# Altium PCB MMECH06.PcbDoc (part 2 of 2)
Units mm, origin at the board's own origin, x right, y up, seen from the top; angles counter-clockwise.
Board outline 65 x 56.01 mm, 4 copper layers (Top Layer, Ground Plane, Mid Layer 1, Bottom Layer), stack 1.442 mm thick; 107 components, 79 nets, 362 pads, 608 vias.
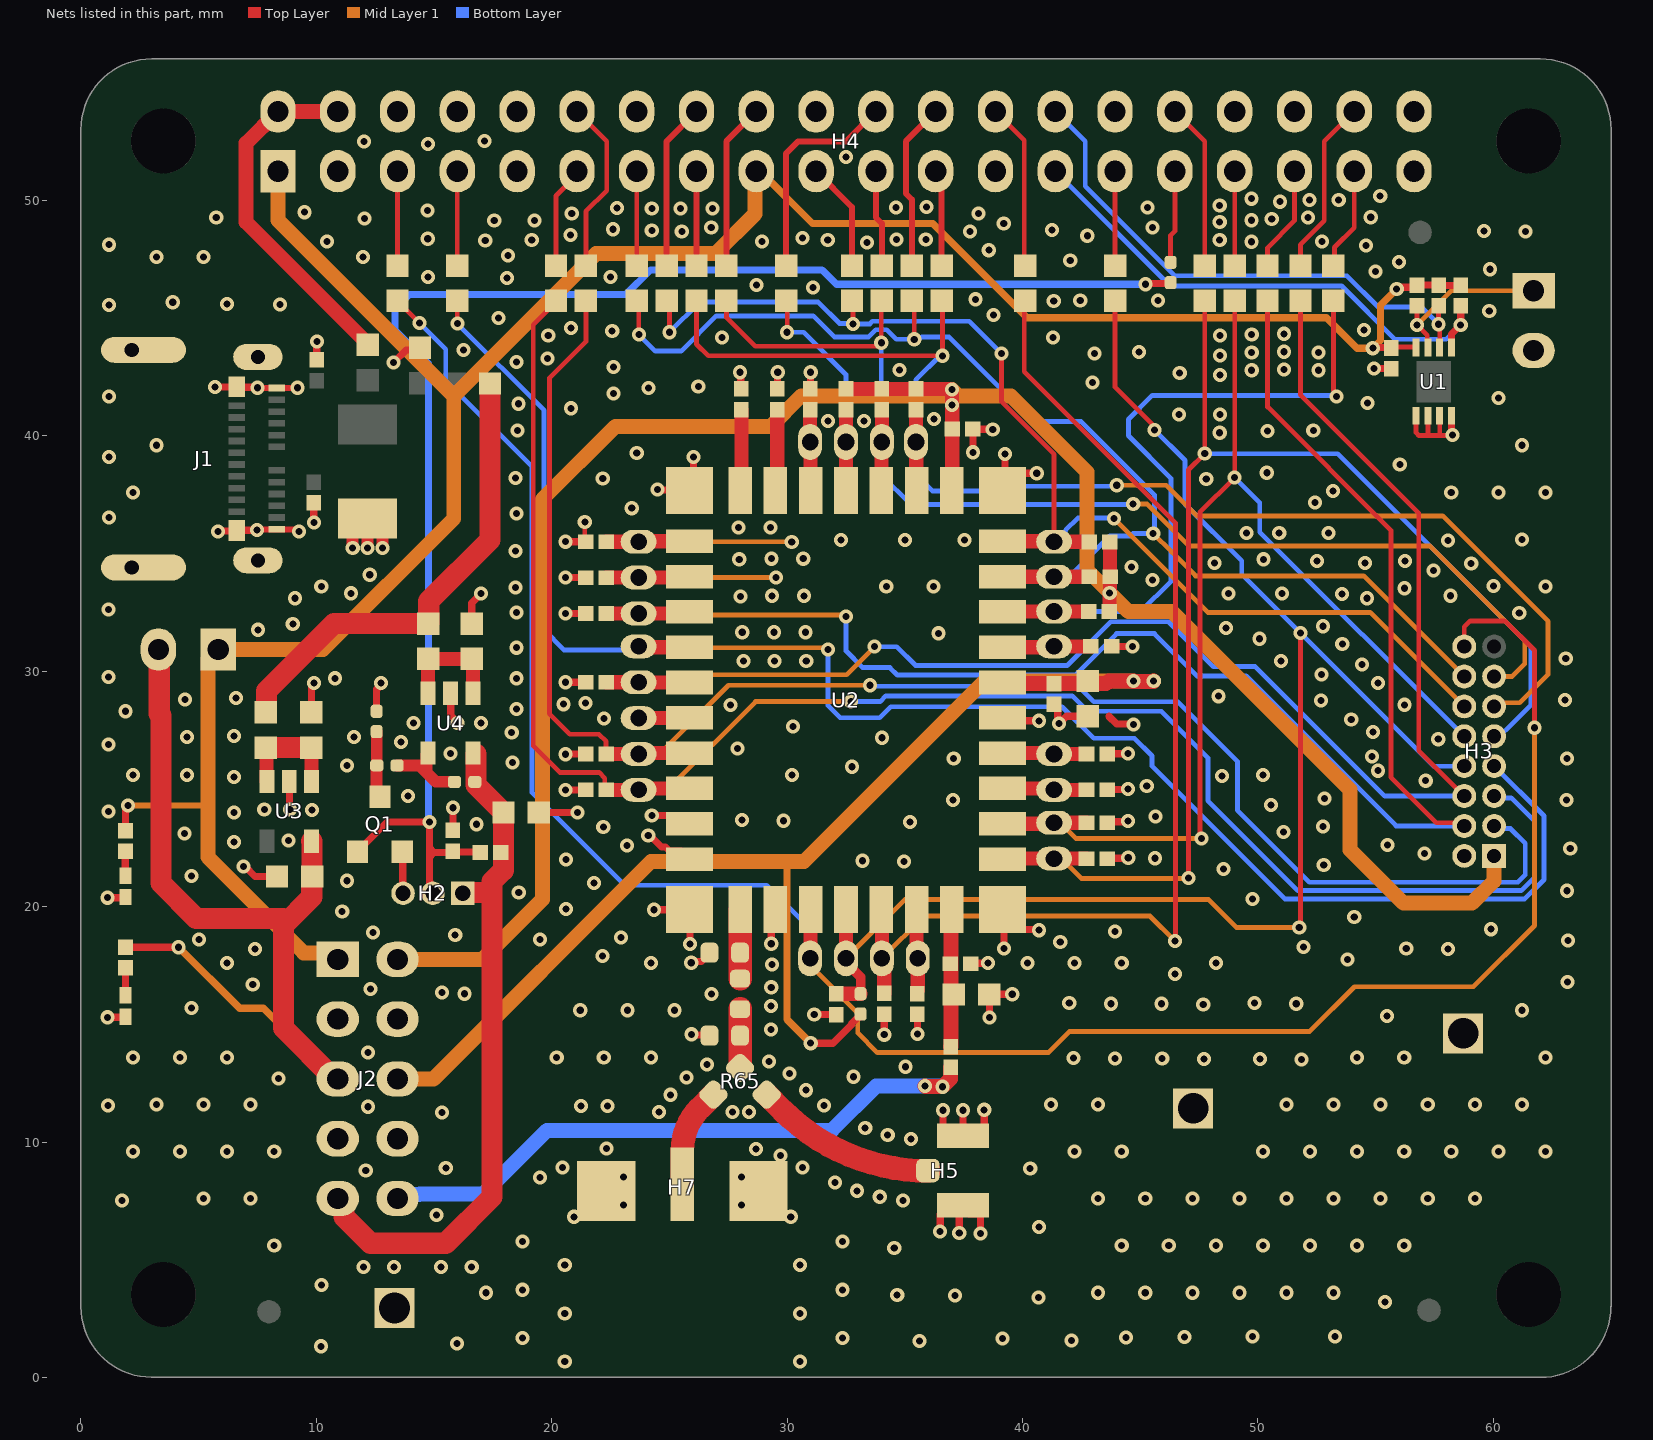
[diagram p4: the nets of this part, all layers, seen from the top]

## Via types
v1: diameter 0.6, hole 0.3, Top Layer to Bottom Layer, tented both sides, 608 vias

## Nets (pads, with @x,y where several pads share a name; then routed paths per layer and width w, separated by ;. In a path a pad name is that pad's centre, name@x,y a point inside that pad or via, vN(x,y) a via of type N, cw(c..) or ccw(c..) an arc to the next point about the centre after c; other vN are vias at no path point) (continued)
GND: C1.2 C2.2 C3.2 C4.1 C5.2 C6.2 C7.2 C8.1 C9.1 C10.1 C11.1 C16.2 D1.K D2.K H1.2 H2.3 H3.2 H4.6 H4.9 H4.14 H4.20 H4.25 H4.30 H4.34 H4.39 H5.2 H5.3 H7.2 J1.A1 J1.A12 J1.B1 J1.B12 J1.SH1 J1.SH2 J1.SH3 J1.SH4 J2.3 J2.4 J2.7 J2.8 Q1.2 R4.2 R5.2 R6.2 R7.2 R8.2 R9.2 R10.2 R11.2 R12.2 R13.2 R14.2 R15.2 R16.2 R18.2 R20.2 R24.2 R52.2 R58.1 R59.2 R60.2 R63.2 R64.2 TP1.1 TP6.1 TP7.1 U1.1 U1.2 U1.3 U1.4 U2.1 U2.2 U2.3 U2.12 U2.20 U2.26 U2.31 U2.37 U3.2 U4.2 VS1.A | length 87
  Top Layer w0.203: v1(21.405,36.344) 21.405,35.536 R13.2@21.439,35.502 ; U1.1@56.718,40.85 56.718,40.133 56.837,40.014 57.163,40.014 ; U1.2@57.218,40.85 57.218,40.069 57.163,40.014 ; U1.3@57.718,40.85 57.718,40.018 57.722,40.014 ; v1(58.256,40.04) 58.23,40.014 57.722,40.014 ; 57.163,40.014 57.722,40.014
  Top Layer w0.254: v1(7.506,42.041) 7.512,42.036 8.323,42.036 J1.A1@8.329,42.03 8.335,42.036 9.189,42.036 v1(9.195,42.041) ; v1@7.508,36.028 J1.A12@8.327,36.028 ; J1.A12@8.329,36.03 9.103,36.03 9.192,35.941 v1(9.259,35.941)
  Top Layer w0.305: v1(1.131,15.3) 1.863,15.3 D2.K@1.893,15.33 ; v1(1.131,20.38) D1.K@1.975,20.38 ; v1(5.69,42.073) 5.693,42.077 6.626,42.077 J1.B12@6.629,42.08 6.648,42.061 7.487,42.061 v1(7.506,42.041) ; v1(5.83,35.941) 5.85,35.961 6.609,35.961 J1.B1@6.629,35.98 6.639,35.991 7.471,35.991 v1(7.481,36.001) v1@7.508,36.028 ; v1(6.9,21.7) 6.978,21.7 7.396,21.281 C9.1@8.329,21.281 ; U3.2@8.85,25.32 8.863,25.307 8.863,24.139 v1(8.875,24.126) ; C8.1@9.79,28.254 9.79,29.31 9.9,29.42 v1(9.9,29.5) ; v1(9.894,36.322) R60.2@9.894,37.16 ; R59.2@10.021,43.215 v1(10.021,44.002) ; VS1.A@11.254,36.363 11.381,36.49 11.39,36.481 VS1.A@12.18,36.481 ; VS1.A@12.143,36.444 VS1.A@12.18,36.481 ; R52.2@12.562,28.299 12.562,29.233 12.75,29.42 v1(12.75,29.5) ; VS1.A@12.798,35.863 VS1.A@12.18,36.481 ; v1(13.284,43.115) 13.818,43.648 14.491,43.648 C16.2@14.402,43.738 ; Q1.2@13.65,22.325 13.675,22.3 13.675,20.525 H2.3@13.7,20.5 ; U4.2@15.7,29.07 15.713,29.057 15.713,28.117 16,27.83 v1(16,27.8) ; R64.2@15.8,23.24 v1(15.8,24.2) ; C11.1@16.6,32.025 16.6,32.9 v1(17,33.3) ; C10.1@19.45,24 v1(21.1,24) ; v1(20.587,24.949) 20.594,24.955 21.46,24.955 R15.2@21.466,24.961 ; v1@20.613,26.473 20.619,26.479 21.434,26.479 R16.2@21.443,26.489 ; v1@20.861,29.533 R18.2@21.466,29.533 ; v1@20.861,32.454 R20.2@21.466,32.454 ; v1@20.861,33.978 R14.2@21.466,33.978 ; v1@20.861,35.502 R13.2@21.439,35.502 ; v1(24.1,23.025) 24.18,23.025 24.667,22.537 24.834,22.537 25.002,22.369 25.51,22.369 U2.2@25.858,22.021 ; v1(24.25,23.875) 24.256,23.869 25.502,23.869 U2.3@25.85,23.521 ; v1(24.347,19.869) 25.705,19.869 25.871,19.703 v1(25.871,18.421) ; v1(24.489,37.721) 24.509,37.702 U2.12@25.895,37.702 ; v1(25.927,17.618) 25.983,17.674 26.359,17.674 26.551,17.866 R58.1@26.551,18.037 ; v1(25.933,14.578) 25.961,14.549 26.678,14.549 R63.2@26.7,14.571 ; U2.12@26.023,37.844 v1(26.023,39.104) ; v1(28,42.7) 28.028,42.672 28.028,42.11 R12.2@28.055,42.082 ; v1(29.325,18.425) 29.325,19.854 U2.37@29.5,20.029 ; R11.2@29.579,41.982 29.59,41.993 29.59,42.69 v1(29.6,42.7) ; R10.2@30.976,42.082 30.988,42.094 30.988,42.688 v1(31,42.7) ; v1(31.15,15.425) 31.155,15.42 C7.2@32.089,15.42 ; R4.2@33.964,15.373 34.126,15.211 v1(34.126,14.56) ; v1(35.533,14.598) R24.2@35.533,15.436 ; v1(36.496,6.208) 36.503,6.215 36.503,6.942 36.638,7.076 37.698,7.076 H5.3@37.698,7.237 ; v1(36.62,11.352) 36.62,10.637 36.706,10.551 H5.2@36.73,10.551 ; v1(37.31,6.137) H5.3@37.31,6.942 ; H5.2@37.451,10.264 37.61,10.637 37.469,10.637 v1(37.469,11.352) ; H5.3@37.698,6.942 38.176,6.942 H5.3@38.4,7.166 ; C2.2@37.796,17.584 37.807,17.595 38.517,17.595 v1(38.532,17.61) ; C6.2@37.893,40.29 37.905,40.278 38.723,40.278 v1(38.735,40.267) ; v1(37.9,39.3) 37.897,39.303 37.897,40.294 C6.2@37.9,40.297 ; v1(38.211,6.12) 38.211,6.942 H5.3@38.229,6.942 ; H5.2@38.37,10.097 v1(38.37,11.37) ; v1(38.596,15.287) C3.2@38.596,16.233 ; C3.2@38.596,16.458 C3.2@38.641,16.503 ; C3.2@38.641,16.278 v1(39.561,16.278) ; U2.31@39.15,19.871 39.998,19.023 40.677,19.023 v1(40.7,19) ; U2.26@39.15,28.021 39.276,27.895 v1(40.704,27.895) ; U2.20@39.15,37.671 39.256,37.777 v1(39.256,39.223) ; v1(39.218,18.219) U2.31@39.218,19.796 ; U2.20@39.231,37.76 39.882,38.411 v1(40.603,38.411) ; C4.1@41.334,28.598 41.491,28.44 41.491,27.917 41.555,27.853 v1(41.555,27.773) 41.87,28.088 C5.2@42.766,28.088 ; R5.2@43.589,22.04 43.608,22.059 44.47,22.059 v1(44.489,22.078) ; R6.2@43.589,23.564 43.628,23.604 44.443,23.604 v1(44.482,23.644) ; R7.2@43.589,24.961 43.605,24.978 44.466,24.978 v1(44.482,24.995) ; R8.2@43.589,26.485 43.599,26.495 44.472,26.495 v1(44.482,26.506) ; 43.666,28.088 43.988,27.766 44.694,27.766 v1(44.717,27.743) ; R9.2@43.773,31.057 43.779,31.051 44.66,31.051 v1(44.667,31.045) ; v1(54.928,42.859) 54.932,42.855 55.661,42.855 C1.2@55.665,42.859 ; U1.4@58.218,40.85 58.218,40.077 v1(58.256,40.04)
  Top Layer w0.508: v1(11.545,35.243) VS1.A@11.545,36.481 ; v1(12.18,35.243) VS1.A@12.18,36.481 ; v1(12.815,35.243) VS1.A@12.815,36.481
  other v1: 20.552,0.675 30.552,0.675 10.2,1.325 15.975,1.45 35.625,1.55 42.075,1.575 39.15,1.65 18.752,1.675 32.352,1.675 44.4,1.7 46.875,1.725 49.772,1.743 53.267,1.743 20.552,2.725 30.552,2.725 55.4,3.2 40.675,3.4 37.125,3.475 34.675,3.5 17.211,3.599 43.211,3.599 45.211,3.599 47.211,3.599 49.211,3.599 51.211,3.599 53.211,3.599 18.752,3.725 32.352,3.725 10.225,3.925 12,4.7 13.3,4.7 15.3,4.7 16.6,4.7 20.552,4.775 30.552,4.775 34.55,5.5 8.211,5.599 44.211,5.599 46.211,5.599 48.211,5.599 50.211,5.599 52.211,5.599 54.211,5.599 56.211,5.599 18.752,5.775 32.352,5.775 40.7,6.4 20.952,6.825 30.152,6.825 15.1,6.9 23.052,7.325 28.052,7.325 1.75,7.525 34.923,7.518 5.211,7.599 7.211,7.599 43.211,7.599 45.211,7.599 47.211,7.599 49.211,7.599 51.211,7.599 53.211,7.599 55.211,7.599 57.211,7.599 59.211,7.599 33.935,7.675 32.968,7.93 32.031,8.279 19.5,8.5 23.052,8.525 28.052,8.525 12.1,8.8 40.325,8.875 15.5,8.9 20.452,8.925 30.652,8.925 29.725,9.425 2.211,9.599 4.211,9.599 6.211,9.599 8.211,9.599 42.211,9.599 44.211,9.599 50.211,9.599 52.211,9.599 54.211,9.599 56.211,9.599 58.211,9.599 60.211,9.599 62.211,9.599 28.675,9.7 22.325,9.725 35.256,10.123 34.271,10.299 33.316,10.595 15.338,11.25 24.553,11.27 27.675,11.275 28.386,11.27 12.2,11.5 21.25,11.525 22.368,11.525 1.15,11.55 31.57,11.559 3.211,11.599 5.211,11.599 7.211,11.599 41.211,11.599 43.211,11.599 51.211,11.599 53.211,11.599 55.211,11.599 57.211,11.599 59.211,11.599 61.211,11.599 25.051,12.007 30.804,12.203 8.4,12.7 25.732,12.74 32.825,12.775 30.098,12.91 35.025,13.2 26.6,13.299 29.236,13.418 51.85,13.5 47.7,13.525 50.082,13.525 43.925,13.55 45.932,13.55 42.157,13.575 2.211,13.599 4.211,13.599 6.211,13.599 20.211,13.599 22.211,13.599 24.211,13.599 54.211,13.599 56.211,13.599 62.211,13.599 12.2,13.8 29.317,14.781 55.475,15.35 21.211,15.599 23.211,15.599 25.211,15.599 61.211,15.599 4.7,15.7 29.315,15.781 47.675,15.85 43.75,15.875 45.907,15.875 51.625,15.875 41.982,15.9 49.857,15.9 16.3,16.3 26.794,16.289 15.338,16.35 12.3,16.5 29.325,16.575 7.3,16.7 63.15,16.8 46.47,17.145 29.35,17.55 6.211,17.599 24.211,17.599 40.211,17.599 42.211,17.599 44.211,17.599 48.211,17.599 53.8,17.75 22.15,17.9 7.4,18.2 58.068,18.2 56.3,18.225 51.931,18.288 41.6,18.5 63.175,18.568 5.018,18.598 19.5,18.6 22.94,18.69 15.9,18.8 12.4,18.9 43.93,18.945 59.897,19.042 54.09,19.558 11.1,19.8 20.6,19.9 49.775,20.325 18.6,20.6 63.125,20.675 21.8,21 11.3,21.1 4.7,21.3 48.543,21.593 52.795,21.777 34.968,21.925 33.2,21.95 20.6,22 45.625,22.057 57.075,22.25 63.265,22.477 23.2,22.6 55.5,22.625 6.5,22.75 8.814,22.804 4.4,23.1 51.084,23.176 22.19,23.39 52.769,23.403 16.8,23.5 35.211,23.599 29.843,23.65 28.075,23.675 45.65,23.825 6.5,24 1.168,24.039 9.815,24.101 7.789,24.129 50.55,24.325 37.05,24.525 63.1,24.525 52.825,24.6 13.9,24.7 45.275,25.125 57.125,25.35 6.5,25.5 48.475,25.55 2.211,25.599 4.5,25.6 30.211,25.599 50.211,25.599 55.096,25.775 32.757,25.943 11.3,26 18.329,26.129 37.075,26.293 63.125,26.293 54.839,26.376 20.587,26.473 15.7,26.5 27.898,26.716 1.168,26.884 13.6,27 57.658,27.113 34.025,27.175 4.5,27.2 11.6,27.2 6.5,27.25 18.3,27.4 54.889,27.418 30.25,27.65 14.126,27.8 17,27.8 53.963,27.954 22.225,27.998 1.9,28.3 18.5,28.4 27.589,28.569 56.225,28.575 20.5,28.6 21.438,28.659 52.68,28.764 63.05,28.775 4.421,28.805 6.587,28.865 48.324,28.94 55.096,29.499 20.587,29.533 10.8,29.7 18.5,29.7 1.168,29.754 52.705,29.856 54.42,30.286 28.143,30.437 29.464,30.437 30.81,30.437 50.978,30.44 63.075,30.543 18.5,31 53.582,31.15 50.063,31.38 36.437,31.612 28.092,31.656 29.439,31.656 30.785,31.656 7.518,31.761 48.641,31.837 52.769,31.912 9,32 20.587,32.454 61.1,32.475 18.5,32.5 1.168,32.625 9.1,33.1 54.625,33.1 28.016,33.18 29.362,33.205 30.709,33.205 58.179,33.207 53.575,33.275 11.481,33.31 48.75,33.3 51.025,33.3 56.225,33.525 18.454,33.563 10.211,33.599 34.211,33.599 36.211,33.599 62.211,33.599 60,33.625 45.525,33.875 20.587,33.978 12.268,34.098 57.455,34.276 44.633,34.426 59.058,34.58 48.158,34.604 54.547,34.601 52.502,34.682 56.25,34.675 27.965,34.755 50.228,34.755 29.337,34.78 30.683,34.78 18.454,35.112 20.587,35.502 58.075,35.55 32.283,35.568 35.001,35.568 37.541,35.568 61.211,35.599 49.518,35.871 50.902,35.871 53,35.875 27.94,36.101 29.286,36.101 1.194,36.536 18.5,36.7 23.4,36.925 52.425,37.175 2.211,37.599 58.211,37.599 60.211,37.599 62.211,37.599 53.192,37.659 47.803,38.162 22.168,38.193 18.454,38.211 50.375,38.432 56.025,38.775 1.194,39.102 23.61,39.265 3.211,39.599 61.211,39.599 48.375,40.132 50.4,40.2 18.542,40.219 52.35,40.225 31.738,40.637 33.262,40.637 36.234,40.713 46.65,40.907 48.387,40.905 20.816,41.17 18.593,41.362 54.65,41.4 60.211,41.599 1.194,41.667 22.625,41.8 24.118,42.029 26.226,42.089 42.977,42.269 48.387,42.581 46.675,42.675 49.733,42.785 52.578,42.785 34.775,42.8 51.105,42.81 22.625,42.918 18.505,43.138 19.825,43.291 48.387,43.42 43.053,43.496 49.733,43.547 52.578,43.547 44.946,43.561 51.105,43.572 16.256,43.648 27.225,44.175 41.3,44.182 19.851,44.256 48.387,44.258 49.733,44.309 51.105,44.334 22.569,44.459 54.5,44.5 20.816,44.577 17.742,45 38.765,45.135 59.825,45.307 1.194,45.553 8.45,45.575 6.211,45.599 3.9,45.675 41.325,45.725 42.45,45.75 45.75,45.75 38,45.8 31.1,46.3 28.7,46.4 18.1,46.7 14.75,46.75 22.5,46.75 54.992,46.985 59.85,47.075 55.992,47.385 42.025,47.447 3.211,47.599 5.211,47.599 11.975,47.6 18.15,47.668 38.565,47.885 54.592,48.085 1.194,48.119 33.389,48.218 10.45,48.25 28.925,48.25 49.721,48.244 52.725,48.25 17.175,48.3 19.15,48.325 31.725,48.325 48.375,48.32 34.646,48.347 35.89,48.347 14.732,48.373 30.65,48.4 42.75,48.5 20.8,48.525 25.525,48.675 37.775,48.675 61.368,48.675 59.6,48.7 24.25,48.725 41.25,48.75 22.6,48.775 26.775,48.85 45.525,48.85 39.2,49.025 48.375,49.082 17.557,49.15 19.275,49.15 49.721,49.158 50.585,49.209 12.05,49.225 5.75,49.275 52.125,49.275 54.792,49.285 20.85,49.45 38.125,49.45 9.5,49.5 14.725,49.575 24.25,49.65 25.475,49.65 26.825,49.65 22.775,49.675 34.62,49.693 45.3,49.7 35.916,49.719 48.375,49.784 50.94,49.946 52.185,50.022 53.43,50.022 49.721,50.073 55.192,50.185 32.5,51.851 14.75,52.4 12.025,52.5 17.15,52.525
MM_GPIO0: pad.16 R4.1 R30.1 U2.34 | length 46.5
  Top Layer w0.203: U2.34@34,20.016 cw(c34,19.992) U2.34@34.024,19.992 ; R30.1@40.076,45.682 40.076,42.724 46.495,36.305 46.495,18.568 v1(46.47,18.543)
  Top Layer w0.6: pad.16@34.024,17.803 34.024,17.436 34.124,17.337 R4.1@34.124,16.316 ; pad.16@34.024,18.535 U2.34@34.024,19.992
  Mid Layer 1 w0.203: pad.16@34.024,17.803 35.821,19.6 45.413,19.6 v1(46.47,18.543)
MM_GPIO1: pad.17 R24.1 U2.33 | length 3.3
  Top Layer w0.203: pad.17@35.5,17.851 pad.17@35.548,17.803
  Top Layer w0.6: pad.17@35.5,18.001 U2.33@35.5,19.871 ; R24.1@35.548,16.457 pad.17@35.548,17.803
MM_GPIO2: H3.9 pad.19 R5.1 R28.1 U2.30 | length 55.8
  Top Layer w0.203: U2.30@39,22.016 cw(c39.024,22.016) U2.30@39.024,22.04 ; v1(47.049,21.218) 47.049,38.552 v1(47.74,39.243) R28.1@47.74,45.682
  Top Layer w0.6: U2.30@39.324,22.04 pad.19@40.877,22.04 ; pad.19@41.341,22.04 R5.1@42.717,22.04
  Mid Layer 1 w0.203: pad.19@41.191,22.04 pad.19@41.266,22.115 ; pad.19@41.341,22.04 41.66,22.04 42.5,21.2 47.031,21.2 v1(47.049,21.218) v1@46.999,21.269
  Bottom Layer w0.203: v1(47.74,39.243) 53.388,39.243 61.583,31.048 61.583,28.559 60.519,27.495 60.511,27.495 60.254,27.238 H3.9@60.034,27.238
MM_GPIO3: H3.10 pad.20 R6.1 R29.1 U2.29 | length 48.3
  Top Layer w0.203: v1(47.603,22.9) 47.537,22.967 47.537,36.754 v1(49.01,38.227) R29.1@49.01,45.682
  Top Layer w0.6: U2.29@39.3,23.521 pad.20@41.139,23.521 ; pad.20@41.341,23.564 R6.1@42.717,23.564
  Mid Layer 1 w0.203: pad.20@41.191,23.564 pad.20@41.266,23.639 ; pad.20@41.341,23.564 41.595,23.564 42.259,22.9 v1(47.603,22.9)
  Bottom Layer w0.203: v1(49.01,38.227) 50.072,37.165 50.072,35.904 54.404,31.573 54.429,31.573 H3.10@58.764,27.238
MM_GPIO4: pad.21 R7.1 U2.28 | length 3.2
  Top Layer w0.6: U2.28@39.3,25.021 pad.21@41.122,25.021 ; pad.21@41.341,24.961 R7.1@42.717,24.961
MM_GPIO5: pad.22 R8.1 U2.27 | length 3.2
  Top Layer w0.6: U2.27@39.3,26.521 pad.22@41.146,26.521 ; pad.22@41.341,26.485 R8.1@42.717,26.485
MM_GPIO6: pad.24 R9.1 U2.24 | length 3.4
  Top Layer w0.6: U2.24@39.3,31.021 pad.24@41.146,31.021 ; pad.24@41.309,31.057 R9.1@42.909,31.057
MM_GPIO7: pad.34 R10.1 U2.15 | length 3.3
  Top Layer w0.6: pad.34@30.976,39.739 R10.1@30.976,40.958 ; U2.15@31,37.671 30.988,37.683 30.988,39.703 pad.34@31,39.715
MM_GPIO8: R11.1 U2.14 | length 3.5
  Top Layer w0.6: U2.14@29.5,37.671 29.579,37.75 R11.1@29.579,41.11
MM_GPIO9: R12.1 U2.13 | length 3.5
  Top Layer w0.6: U2.13@28,37.671 28.055,37.726 R12.1@28.055,41.11
MM_GPIO10: pad.2 R13.1 U2.11 | length 9.7
  Top Layer w0.6: R13.1@22.319,35.502 pad.2@23.691,35.502 ; pad.2@23.837,35.521 U2.11@25.7,35.521
  Mid Layer 1 w0.203: pad.2@23.682,35.5 30.193,35.5 v1(30.195,35.497)
MM_GPIO11: pad.3 R14.1 U2.10 | length 9.4
  Top Layer w0.6: R14.1@22.326,33.978 pad.3@23.672,33.978 ; pad.3@23.691,33.978 25.807,33.978 U2.10@25.85,34.021
  Mid Layer 1 w0.203: pad.3@23.691,33.983 29.515,33.983 v1(29.521,33.989)
MM_JTAG_TCK: H3.5 pad.12 R15.1 R42.1 U2.4 | length 75.6
  Top Layer w0.203: R42.1@20.181,45.682 20.131,45.682 19.808,45.359 19.808,45.309 19.216,44.717 19.216,26.826 20.342,25.7 22.01,25.7 22.253,25.457 22.253,25.019 R15.1@22.311,24.961
  Top Layer w0.6: R15.1@22.326,24.961 pad.12@23.672,24.961 ; pad.12@23.878,25.021 U2.4@25.7,25.021
  Mid Layer 1 w0.203: pad.12@23.691,24.961 24.911,24.961 28.66,28.71 v1(32.703,28.71)
  Bottom Layer w0.203: v1(32.703,28.71) 33.95,28.71 34.193,28.953 42.115,28.953 42.768,28.3 45.9,28.3 47.875,26.325 47.875,24.508 51.698,20.685 61.188,20.685 61.75,21.247 61.75,23.629 60.758,24.62 60.111,24.62 H3.5@60.034,24.698
MM_JTAG_TDI: H3.3 pad.11 R16.1 R44.1 U2.5 | length 71.4
  Top Layer w0.203: R44.1@21.451,45.682 21.451,44.002 19.9,42.451 19.9,28.2 20.775,27.325 22.002,27.325 22.311,27.016 R16.1@22.311,26.485
  Top Layer w0.6: R16.1@22.326,26.485 pad.11@23.672,26.485 ; pad.11@23.854,26.521 U2.5@25.7,26.521
  Mid Layer 1 w0.203: pad.11@23.691,26.485 23.741,26.535 24.638,26.535 27.509,29.406 v1(33.516,29.406)
  Bottom Layer w0.203: v1(33.516,29.406) 33.562,29.36 42.372,29.36 43.032,28.7 46.6,28.7 49.125,26.175 49.125,24.1 52.185,21.04 61.04,21.04 61.35,21.35 61.35,22.696 60.727,23.319 60.143,23.319 H3.3@60.034,23.428
MM_JTAG_TDO: H3.4 pad.7 R20.1 R45.1 U2.9 | length 71
  Top Layer w0.203: R45.1@50.407,45.682 50.407,41.227 55.65,35.984 55.65,25.5 57.583,23.567 58.625,23.567 H3.4@58.764,23.428
  Top Layer w0.6: R20.1@22.326,32.454 pad.7@23.672,32.454 ; pad.7@23.691,32.454 25.783,32.454 U2.9@25.85,32.521
  Mid Layer 1 w0.203: pad.7@23.691,32.39 32.437,32.39 v1(32.5,32.327)
  Bottom Layer w0.203: v1(32.5,32.327) 32.5,30.862 33.204,30.158 34.367,30.158 34.687,29.838 42.232,29.838 43.993,31.599 45.601,31.599 47.401,29.799 49.497,29.799 55.868,23.428 H3.4@58.764,23.428
MM_JTAG_TMS: H3.6 pad.4 R18.1 R43.1 U2.7 | length 67
  Top Layer w0.203: pad.4@23.672,29.533 pad.4@23.684,29.521 ; R43.1@51.804,45.682 51.804,41.746 56.833,36.717 56.833,26.628 H3.6@58.764,24.698
  Top Layer w0.6: R18.1@22.326,29.533 pad.4@23.672,29.533 ; pad.4@23.83,29.521 U2.7@25.7,29.521
  Mid Layer 1 w0.203: pad.4@23.697,29.533 25.895,29.533 26.213,29.851 32.522,29.851 v1(33.715,31.043)
  Bottom Layer w0.203: v1(33.715,31.043) 34.657,31.043 35.456,30.244 41.899,30.244 43.755,32.1 46.2,32.1 48.1,30.2 49.888,30.2 55.39,24.698 H3.6@58.764,24.698
MM_JTAG_TRST: H3.7 pad.9 R46.1 U2.8 | length 72.8
  Top Layer w0.203: v1(15.99,44.764) R46.1@15.99,45.682 ; pad.9@23.672,31.057 pad.9@23.708,31.021
  Top Layer w0.6: pad.9@23.854,31.021 U2.8@25.7,31.021
  Mid Layer 1 w0.203: pad.9@23.709,30.993 31.675,30.993 v1(31.738,30.93)
  Bottom Layer w0.203: v1(15.99,44.764) 19.673,41.081 19.673,31.753 20.519,30.907 pad.9@23.841,30.907 ; v1(31.738,30.93) 31.738,28.537 32.25,28.025 33.925,28.025 34.396,28.496 41.676,28.496 43.022,27.15 44.75,27.15 45.5,26.4 45.5,25.963 51.134,20.329 61.335,20.329 62.15,21.144 62.15,23.852 H3.7@60.034,25.968
MM_RESET_N: C7.1 H3.8 pad.15 R47.2 R49.1 U2.35 | length 64.9
  Top Layer w0.203: R49.1@44.2,45.462 R49.1@43.93,45.732 43.93,42.07 45.6,40.4 v1(45.6,40.256) ; v1(51.753,19.11) 51.804,19.161 v1(51.804,31.623)
  Top Layer w0.4: pad.15@32.5,17.803 32.5,17.633 33.12,17.013 R47.2@33.12,16.308
  Top Layer w0.6: C7.1@32.308,16.302 R47.2@33.115,16.302 ; pad.15@32.5,17.953 U2.35@32.5,19.871
  Mid Layer 1 w0.203: pad.15@32.5,17.803 34.997,20.3 47.9,20.3 49.09,19.11 v1(51.753,19.11) v1@51.74,19.097
  Bottom Layer w0.203: v1(45.6,40.256) 46.9,38.956 46.9,37.1 49.314,34.686 49.314,34.113 57.459,25.968 H3.8@58.764,25.968
MM_SD_CLK: H3.11 pad.35 R17.2 R32.2 R33.1 U2.18 | length 58.3
  Top Layer w0.203: R33.1@26.15,45.682 26.15,43.9 26.65,43.4 v1(36.6,43.4) 36.6,45.646 R32.2@36.564,45.682
  Top Layer w0.6: U2.18@35.473,37.698 35.486,37.712 35.486,39.725 pad.35@35.473,39.739 ; pad.35@35.473,39.817 R17.2@35.473,41.036
  Mid Layer 1 w0.203: v1(44,37.9) 46.1,37.9 47.4,36.6 57.85,36.6 62.325,32.125 62.325,29.866 61.122,28.664 60.189,28.664 H3.11@60.034,28.508
  Bottom Layer w0.203: v1(36.6,43.4) 36.494,43.4 35.473,42.379 pad.35@35.473,39.739 35.473,38.352 36.165,37.659 39.908,37.659 40.106,37.857 43.957,37.857 v1(44,37.9)
MM_SD_CMD: H3.12 pad.31 R19.2 R34.2 R35.1 U2.21 | length 51.3
  Top Layer w0.203: R35.1@24.88,45.682 25,45.562 v1(25,44.4) ; R34.2@32.754,45.682 32.8,45.636 v1(32.8,44.754) ; v1(39.1,43.5) 39.1,41.463 41.341,39.222 pad.31@41.341,35.502 41.3,35.502 pad.31@41.281,35.521 ; R19.2@42.774,35.502 R19.2@42.782,35.502
  Top Layer w0.6: U2.21@39.3,35.521 pad.31@41.154,35.521 ; pad.31@41.341,35.502 R19.2@42.774,35.502
  Mid Layer 1 w0.203: v1(43.891,36.482) 47.873,32.5 54.772,32.5 H3.12@58.764,28.508
  Bottom Layer w0.203: v1(25,44.4) 26.282,45.682 31.318,45.682 32.224,44.776 32.778,44.776 v1(32.8,44.754) ; v1@32.864,44.764 32.873,44.754 33.514,44.754 33.623,44.864 37.736,44.864 v1(39.1,43.5) ; pad.31@41.341,35.502 41.375,35.502 41.839,35.966 41.839,36 42.344,36.506 43.868,36.506 v1(43.891,36.482)
MM_SD_D0: H3.13 pad.30 R21.1 R36.2 R37.1 U2.17 | length 51.2
  Top Layer w0.203: R37.1@27.42,45.682 27.42,45.03 28.648,43.802 33.948,43.802 v1@34,43.854 ; v1@34,43.9 34,45.658 R36.2@34.024,45.682
  Top Layer w0.6: U2.17@34.024,37.695 34.012,37.707 34.012,39.727 pad.30@34.024,39.739 ; pad.30@34.024,39.817 R21.1@34.024,41.036
  Mid Layer 1 w0.203: v1(44.7,37.1) 45.3,37.1 47.085,35.315 57.316,35.315 61.329,31.302 61.329,30.311 60.796,29.778 H3.13@60.034,29.778
  Bottom Layer w0.203: v1(34,43.954) 34,43.295 33.998,43.293 33.998,38.328 35.241,37.085 44.685,37.085 v1(44.7,37.1)
MM_SD_D1: pad.29 R22.1 R38.1 U2.16 | length 10.7
  Top Layer w0.203: R38.1@29.96,45.732 30,45.692 v1(30,44.4)
  Top Layer w0.6: U2.16@32.5,37.671 pad.29@32.5,39.739 R22.1@32.5,41.036
  Bottom Layer w0.203: v1(30,44.4) 30.7,44.4 32.5,42.6 pad.29@32.5,39.839
MM_SD_D2: pad.27 R23.1 R39.1 U2.23 | length 29.9
  Top Layer w0.203: pad.27@41.214,32.539 pad.27@41.341,32.539 ; R23.1@42.806,32.539 R23.1@42.814,32.539 ; R39.1@53.204,45.732 53.204,41.913 53.334,41.783 v1(53.334,41.675)
  Top Layer w0.6: U2.23@39.248,32.539 pad.27@41.087,32.539 ; pad.27@41.341,32.539 R23.1@42.806,32.539
  Bottom Layer w0.203: pad.27@41.341,32.539 45.029,32.539 46.3,33.811 46.3,38.2 44.5,40 44.5,40.7 45.516,41.716 53.293,41.716 v1(53.334,41.675)
MM_SD_D3: H3.14 pad.25 R25.2 R40.2 R41.1 U2.22 | length 55.2
  Top Layer w0.203: R41.1@23.61,45.682 23.7,45.592 v1(23.7,44.3) ; R40.2@35.294,45.732 35.4,45.626 v1(35.4,44.1) ; pad.25@41.244,34.013 pad.25@41.341,34.013 ; R25.2@42.836,34.013 R25.2@42.844,34.013
  Top Layer w0.6: U2.22@39.302,34.013 pad.25@41.117,34.013 ; pad.25@41.341,34.013 R25.2@42.836,34.013
  Mid Layer 1 w0.203: v1(45.55,35.85) 46.33,35.07 47.35,34.05 54.492,34.05 H3.14@58.764,29.778
  Bottom Layer w0.203: v1(23.7,44.3) 24.4,43.6 25.5,43.6 26.994,45.094 31.106,45.094 32,44.2 33.463,44.2 33.771,44.508 34.229,44.508 34.637,44.1 v1(35.4,44.1) 35.476,44.176 35.693,44.176 35.717,44.2 36.874,44.2 40.467,40.607 42.493,40.607 45.6,37.5 45.6,35.9 v1(45.55,35.85) 44.677,35.85 44.572,35.745 43.704,35.745 42.127,34.168 41.496,34.168 pad.25@41.341,34.013
MM_WAKE: H3.16 pad.14 R48.1 U2.36 | length 92.8
  Top Layer w0.203: R48.1@13.457,45.675 13.507,45.675 14.39,44.792 v1(14.39,44.789) ; U2.36@30.942,19.174 U2.36@31,19.116 ; U2.36@31,19.266 U2.36@31,20.021 ; H3.16@58.764,31.048 58.764,31.886 59.018,32.14 60.491,32.14 61.75,30.881 v1(61.75,27.6)
  Top Layer w0.6: pad.14@30.976,17.803 30.988,17.815 30.988,19.859 U2.36@31,19.871
  Mid Layer 1 w0.203: pad.14@30.976,17.803 30.976,17.503 33,15.479 33,14.637 33.837,13.8 41.1,13.8 42,14.7 52.2,14.7 54.1,16.6 59.15,16.6 61.75,19.2 v1(61.75,27.6)
  Bottom Layer w0.203: v1(14.39,44.789) 15.5,43.679 15.5,42.347 19.165,38.682 19.165,24.847 23.102,20.91 29.138,20.91 30.901,19.147 30.901,18.178 pad.14@30.976,18.103
NC: pad.10 U2.6 | length 1.9
  Top Layer w0.305: U2.6@25.838,28.009 U2.6@25.85,28.021
  Top Layer w0.6: pad.10@23.818,28.009 U2.6@25.688,28.009
NetC8_2: C8.2 R27.1 U3.1 U3.3 | length 4.8
  Top Layer w0.6: U3.3@7.88,25.338 R27.1@7.88,26.708 ; C8.2@9.796,26.773 9.796,25.326 U3.1@9.802,25.32
  Top Layer w0.9: R27.1@7.859,26.754 C8.2@9.79,26.754
NetC11_2: C11.2 R26.1 U4.1 U4.3 | length 4.4
  Top Layer w0.6: U4.3@14.748,29.07 R26.1@14.747,30.525 ; R26.1@15.1,30.525 C11.2@16.6,30.525 16.653,30.472 U4.1@16.653,29.07
NetD1_A: D1.A R61.1 | length 0.9
  Top Layer w0.305: R61.1@1.881,22.174 1.887,22.168 D1.A@1.887,21.31
NetD2_A: D2.A R62.1 | length 1.2
  Top Layer w0.305: D2.A@1.893,16.23 R62.1@1.893,17.408
NetH2_2: H2.2 Q1.1 R51.2 R64.1 R72.1 | length 65.4
  Top Layer w0.3: Q1.1@11.75,22.325 11.75,22.35 13,23.6 v1(14.8,23.6) 14.8,22.5 ; H2.2@14.97,20.6 14.819,20.751 14.819,21.074 14.8,21.093 14.8,22.1 ; R51.2@16.86,22.3 16.83,22.33 15.83,22.33 R64.1@15.8,22.36 15.74,22.3 15,22.3 ; v1(45.228,46.438) 45.262,46.472 46.256,46.472 R72.1@46.29,46.507 ; 14.8,22.1 15,22.3 ; 14.8,22.1 14.8,22.5 ; 14.8,22.5 15,22.3
  Bottom Layer w0.3: v1(14.8,23.6) 14.768,23.632 14.768,43.076 13.344,44.5 13.344,45.375 13.965,45.996 23.142,45.996 24.191,47.045 31.488,47.045 32.095,46.438 v1(45.228,46.438)
NetH5_1: H5.1 R65.C | length 7.9
  Top Layer w1: R65.C@29.131,12.015 29.79,11.356 ccw(c36.022,17.579) 36.012,8.772 H5.1@35.976,8.789 H5.1@36.017,8.772
NetH7_1: H7.1 R65.B | length 4.4
  Top Layer w1: H7.1@25.55,8.05 25.55,9.644 cw(c28.09,9.644) 26.294,11.44 R65.B@26.869,12.015
NetQ1_3: Q1.3 R50.2 R52.1 | length 2.8
  Top Layer w0.5: R50.2@12.56,26 12.56,24.815 Q1.3@12.7,24.675 ; R50.2@12.568,26 R52.1@12.568,27.436
NetR31_2: R31.2 R50.1 U4.4 | length 3.5
  Top Layer w0.5: R50.1@13.44,26 14.378,26 14.625,25.752 ; U4.4@14.748,26.53 14.68,26.462 14.68,25.807 14.625,25.752 ; R31.2@15.868,25.3 15.864,25.304 15.074,25.304 14.625,25.752
NetR57_1: R57.1 R58.2 U2.38 | length 2.9
  Top Layer w1: R57.1@28,16.946 28,18.021 U2.38@28,19.871
NetR57_2: R57.2 R63.1 R65.A | length 2.5
  Top Layer w1: R65.A@28,13.146 R57.2@28,15.671
Pi_GPIO0: H4.27 R2.2 U1.5 | length 22.4
  Top Layer w0.305: U1.5@58.218,43.75 58.218,44.32 v1(58.611,44.713) R2.2@58.611,45.518 R2.2@58.611,45.526
  Bottom Layer w0.203: H4.27@41.39,51.241 46.267,46.364 53.557,46.364 55.817,44.104 58.002,44.104 v1(58.611,44.713)
Pi_GPIO1: H4.28 R3.2 U1.6 | length 22.9
  Top Layer w0.203: R3.2@57.671,45.526 R3.2@57.671,45.518 v1(57.671,44.739) 57.718,44.692 U1.6@57.718,43.75
  Bottom Layer w0.203: H4.28@41.39,53.781 42.66,52.511 42.66,50.606 46.47,46.796 53.778,46.796 55.099,45.475 56.935,45.475 v1(57.671,44.739)
Pi_GPIO2: H4.3
Pi_GPIO3: H4.5 R48.2 | length 4
  Top Layer w0.203: R48.2@13.45,47.282 H4.5@13.45,51.241
Pi_GPIO4: H4.7 R46.2 | length 4
  Top Layer w0.203: R46.2@15.99,47.282 H4.7@15.99,51.241
Pi_GPIO5: H4.29 R49.2 | length 4
  Top Layer w0.203: R49.2@43.93,47.282 H4.29@43.93,51.241
Pi_GPIO6: H4.31 R72.2 | length 3.9
  Top Layer w0.203: R72.2@46.29,47.37 46.29,48.515 46.47,48.695 H4.31@46.47,51.241
Pi_GPIO7: H4.26 R30.2 | length 7
  Top Layer w0.203: H4.26@38.85,53.781 40.076,52.555 R30.2@40.076,47.282
Pi_GPIO8: H4.24 R40.1 | length 7.1
  Top Layer w0.254: R40.1@35.294,47.282 35.294,50.038 35.04,50.292 35.04,52.511 H4.24@36.31,53.781
Pi_GPIO9: H4.21 R36.1 | length 4.2
  Top Layer w0.254: R36.1@33.834,47.037 R36.1@33.897,46.974 ; H4.21@33.834,51.177 H4.21@33.77,51.241 33.77,49.276 34.024,49.022 R36.1@34.024,47.282
Pi_GPIO10: H4.19 R34.1 | length 4.6
  Top Layer w0.254: H4.19@31.23,51.241 32.754,49.717 R34.1@32.754,47.282
Pi_GPIO11: H4.23 R32.1 | length 4.1
  Top Layer w0.254: H4.23@36.31,51.241 36.548,51.003 36.548,47.248 R32.1@36.564,47.232
Pi_GPIO12: H4.32 R28.2 | length 7
  Top Layer w0.203: H4.32@46.47,53.781 47.74,52.511 R28.2@47.74,47.282
Pi_GPIO13: H4.33 R29.2 | length 4
  Top Layer w0.203: R29.2@49.01,47.282 H4.33@49.01,51.241
Pi_GPIO14: H4.8
Pi_GPIO15: H4.10
Pi_GPIO16: H4.36
Pi_GPIO17: H4.11 R42.2 | length 4.3
  Top Layer w0.203: R42.2@20.181,47.282 20.181,50.202 21.07,51.091 H4.11@21.07,51.241
Pi_GPIO18: H4.12 R44.2 | length 7.4
  Top Layer w0.203: H4.12@21.07,53.781 22.34,52.511 22.34,50.419 21.451,49.53 R44.2@21.451,47.282
Pi_GPIO19: H4.35 R45.2 | length 4.4
  Top Layer w0.203: R45.2@50.407,47.282 50.407,47.99 51.55,49.133 H4.35@51.55,51.241
Pi_GPIO20: H4.38 R43.2 | length 7.4
  Top Layer w0.203: R43.2@51.804,47.282 51.804,48.117 52.82,49.133 52.82,52.511 H4.38@54.09,53.781
Pi_GPIO21: H4.40
Pi_GPIO22: H4.15 R33.2 | length 4
  Top Layer w0.254: R33.2@26.15,47.232 H4.15@26.15,51.241
Pi_GPIO23: H4.16 R35.2 | length 7.1
  Top Layer w0.254: R35.2@24.88,47.232 24.88,52.511 H4.16@26.15,53.781
Pi_GPIO24: H4.18 R37.2 | length 7.1
  Top Layer w0.254: R37.2@27.42,47.232 27.42,52.511 H4.18@28.69,53.781
Pi_GPIO25: H4.22 R38.2 | length 9.3
  Top Layer w0.254: R38.2@29.96,47.232 29.96,52.003 30.468,52.511 32.5,52.511 H4.22@33.77,53.781
Pi_GPIO26: H4.37 R39.2 | length 4.3
  Top Layer w0.203: R39.2@53.25,47.25 53.25,48 54.09,48.84 H4.37@54.09,51.241
Pi_GPIO27: H4.13 R41.2 | length 4
  Top Layer w0.203: R41.2@23.61,47.232 H4.13@23.61,51.241
RPI_ID_WP: H1.1 R1.2 U1.7 | length 7.8
  Top Layer w0.203: R1.2@56.757,45.526 v1(56.757,44.713) 57.194,44.276 57.194,43.774 U1.7@57.218,43.75 ; H1.1@61.52,45.97 H1.1@61.71,46.161
  Mid Layer 1 w0.203: v1(56.757,44.713) 58.205,46.161 H1.1@61.71,46.161
VBAT: C4.2 C5.1 J2.6 R47.1 U2.25 | length 55.8
  Top Layer w0.305: v1(31,14.2) 31.949,14.2 32.745,14.996 32.745,15.033 33.021,15.309 R47.1@33.12,15.309
  Top Layer w0.635: U2.25@39.383,29.478 C5.1@42.584,29.478 ; C5.1@42.879,29.474 43.551,29.474 43.666,29.588 ; 43.727,29.571 43.747,29.592 v1(44.717,29.592) ; v1@44.717,29.571 45.551,29.571 v1(45.571,29.592)
  Mid Layer 1 w0.305: 30,21.925 30,15.2 v1(31,14.2)
  Mid Layer 1 w0.635: J2.6@13.45,12.681 14.981,12.681 24.225,21.925 30,21.925 30.725,21.925 38.392,29.592 v1(44.717,29.592) ; v1@44.717,29.571 45.551,29.571 v1(45.571,29.592)
VDD5: R26.2 R27.2 R56.2 | length 20.3
  Top Layer w0.9: R27.2@7.859,28.254 7.884,28.279 7.884,29.165 10.745,32.025 14.722,32.025 R26.2@14.722,32.05 ; R26.2@14.747,32.025 14.772,32.05 14.772,32.972 17.375,35.575 R56.2@17.375,42.224
VDD5_RPi: H4.2 H4.4 R55.1 | length 15.1
  Top Layer w0.635: H4.4@10.91,53.781 H4.2@8.37,53.781 7.021,52.432 7.021,49.072 R55.1@12.18,43.913
VDD_3V3: C9.2 H6.2 J2.5 R62.2 U3.5 | length 38.7
  Top Layer w0.305: R62.2@1.893,18.272 1.899,18.278 4.147,18.278 v1(4.15,18.275)
  Top Layer w0.9: 3.327,28.533 H6.2@3.327,30.884 ; 3.329,28.532 3.329,28.196 3.4,28.125 3.4,21 4.9,19.5 8.6,19.5 ; U3.5@9.802,22.78 9.816,22.767 9.816,21.294 C9.2@9.829,21.281 9.804,21.256 9.804,20.404 8.6,19.2 8.6,14.841 10.76,12.681 J2.5@10.91,12.681
  Mid Layer 1 w0.305: v1(4.15,18.275) 6.744,15.681 7.76,15.681 10.76,12.681 J2.5@10.91,12.681
VDD_FEM: C10.2 H2.1 J2.9 R31.1 R51.1 U4.5 | length 29.2
  Top Layer w0.9: J2.9@10.91,7.601 11.175,7.336 11.175,6.825 12.3,5.7 15.5,5.7 17.465,7.665 17.465,20.5 17.465,21.065 17.95,21.55 17.95,22.3 C10.2@17.95,24 16.785,25.165 16.785,25.3 U4.5@16.785,26.485 ; H2.1@16.24,20.6 17.465,20.6
VDDIO: C6.1 H3.1 J2.2 R17.1 R19.1 R21.2 R22.2 R23.2 R25.1 U2.19 | length 93.3
  Top Layer w0.305: R23.2@43.677,32.539 R23.2@43.694,32.555
  Top Layer w0.6: R22.2@32.5,41.982 R17.1@35.473,41.982 ; R17.1@35.473,41.99 36.972,41.99 v1(36.996,41.967) v1(36.996,41.306) ; R23.2@43.694,32.555 v1@43.694,33.323 ; v1@43.709,33.386 R25.1@43.709,33.981 ; R25.1@43.716,34.013 R19.1@43.716,35.483
  Top Layer w0.635: U2.19@37.013,37.684 C6.1@37.013,40.29 v1@37.013,41.306
  Mid Layer 1 w0.6: v1(36.996,41.306) v1(36.996,41.967)
  Mid Layer 1 w0.635: J2.2@13.45,17.761 17.061,17.761 19.6,20.3 19.6,37.3 22.7,40.4 29.3,40.4 30.6,41.7 36.729,41.7 v1(36.996,41.967) 37.262,41.7 39.5,41.7 42.745,38.455 42.745,34.287 v1(43.701,33.331) 44.493,32.539 46.341,32.539 53.912,24.968 53.912,22.412 56.173,20.151 59.094,20.151 60.02,21.078 60.02,22.145 H3.1@60.034,22.158
VDDIO_RAPI: C1.1 H4.1 H4.17 H6.1 J2.1 R1.1 R2.1 R3.1 R61.2 U1.8 | length 105.7
  Top Layer w0.203: C1.1@55.356,43.752 55.379,43.776 56.693,43.776 U1.8@56.718,43.75
  Top Layer w0.305: R61.2@1.893,23.233 1.893,24.113 2,24.22 v1(2,24.3) ; v1@54.877,43.748 54.882,43.752 C1.1@55.356,43.752 ; v1(55.893,46.242) 55.973,46.242 56.044,46.313 56.68,46.313 56.769,46.402 57.659,46.402 57.671,46.39 R2.1@58.611,46.39
  Mid Layer 1 w0.254: v1(2,24.3) 5.4,24.3
  Mid Layer 1 w0.305: H4.17@28.69,51.241 28.856,51.241 31.075,49.022 36.183,49.022 40.187,45.018 52.91,45.018 54.205,43.723 v1(54.877,43.723) 54.877,43.726 55.2,44.049 55.2,45.549 v1(55.893,46.242)
  Mid Layer 1 w0.635: H4.1@8.37,51.241 8.37,49.158 15.838,41.691 ; J2.1@10.91,17.761 10.632,18.039 9.461,18.039 5.4,22.1 5.4,24.3 5.4,30.491 H6.1@5.83,30.921 10.275,30.921 15.838,36.484 15.838,41.691 ; H4.17@28.69,51.241 28.635,51.186 28.635,49.424 26.949,47.738 21.885,47.738 15.838,41.691
VFEM: J2.10 L1.2 | length 26.9
  Top Layer w0.635: v1(35.85,12.375) 35.874,12.351 v1(36.601,12.351) 36.938,12.688 36.938,13.165 L1.2@36.946,13.173
  Bottom Layer w0.635: J2.10@13.45,7.601 13.616,7.767 14.371,7.767 14.404,7.8 17.1,7.8 19.8,10.5 31.9,10.5 33.775,12.375 36.577,12.375 v1(36.601,12.351)
VFEM_MM: C2.1 C3.1 L1.1 U2.32 | length 5.8
  Top Layer w0.635: L1.1@36.946,14.053 36.953,14.06 36.953,16.271 36.953,17.57 36.953,19.824 U2.32@37,19.871
pads on no net: FID1.1 FID2.1 FID3.1 H3.15 J1.A2 J1.A3 J1.A6 J1.A7 J1.A8 J1.A10 J1.A11 J1.B2 J1.B3 J1.B6 J1.B7 J1.B8 J1.B10 J1.B11 MH1.1 MH2.1 MH3.1 MH4.1 U1.9 U3.4

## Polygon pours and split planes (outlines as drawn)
GND on Top Layer "GND_L01_P010" (solid, remove dead copper, pour order 10): 0,0.011 64.988,0.011 64.988,56.011 0,56.011
GND on Bottom Layer "GND_L04_P011" (solid, remove dead copper, pour order 11): -0.012,0 64.988,0 64.988,56 -0.012,56
GND on Mid Layer 1 "GND_L03_P012" (solid, remove dead copper, pour order 12): 0,0 65,0 65,56.011 0,56.011
GND on Ground Plane (split plane): 180 vertices, not listed, extent 0.51,0.51 64.49,55.501

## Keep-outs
Keep-Out Layer:
  circle w0.2: c3.5,52.522 r2.8
  circle w0.2: c61.5,52.522 r2.8
  circle w0.2: c61.5,3.522 r2.8
  circle w0.2: c3.5,3.522 r2.8

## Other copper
Top Layer:
  text ".Layer_Name" at 39.7,-2.75 h1.52
Mid Layer 1:
  text ".Layer_Name" at 39.7,-2.75 h1.52
Bottom Layer:
  text ".Layer_Name" at 39.7,-2.75 h1.52
Ground Plane (plane layer: these items are gaps in the copper):
  lines w1.016: 0,2.814 0,3.011 0,53.011 0,53.208 0.051,53.598 0.153,53.977 0.304,54.341 0.5,54.681 0.74,54.993 1.018,55.271 1.33,55.511 1.67,55.707 2.034,55.858 2.413,55.96 2.803,56.011 3,56.011 62,56.011 62.197,56.011 62.587,55.96 62.966,55.858 63.33,55.707 63.67,55.511 63.982,55.271 64.26,54.993 64.5,54.681 64.696,54.341 64.847,53.977 64.949,53.598 65,53.208 65,53.011 64.988,3 64.988,2.803 64.937,2.413 64.835,2.034 64.684,1.67 64.488,1.33 64.248,1.018 63.97,0.74 63.658,0.5 63.318,0.304 62.954,0.153 62.575,0.051 62.185,0 61.988,0 29.117,0.006 29.117,5.275 29.216,5.275 29.4,5.351 29.541,5.492 29.617,5.676 29.617,5.874 29.541,6.058 29.4,6.199 29.216,6.275 29.117,6.275 21.987,6.275 21.888,6.275 21.704,6.199 21.563,6.058 21.487,5.874 21.487,5.676 21.563,5.492 21.704,5.351 21.888,5.275 21.987,5.275 21.987,0.007 3,0.011 2.803,0.011 2.413,0.062 2.034,0.164 1.67,0.315 1.33,0.511 1.018,0.751 0.74,1.029 0.5,1.341 0.304,1.681 0.153,2.045 0.051,2.424 0,2.814
  text ".Layer_Name" at 39.55,-2.9 h1.52

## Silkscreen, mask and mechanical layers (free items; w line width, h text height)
Top Overlay:
  lines w0.2: 22.848,43.688 28.182,43.688 28.182,48.081 22.848,48.081 22.848,43.688 ; 31.992,43.688 31.992,48.006 37.32,48.006 37.32,43.688 31.992,43.688
  text "2" at 5.83,53.4 h0.76
  text "40" at 58.408,53.273 h0.76
  text "1" at 5.83,50.987 h0.76
  text "39" at 58.662,50.733 h0.76
  text "9" at 18.276,48.955 h0.76
  text "29" at 41.898,48.955 h0.76
  text "19" at 30.722,48.828 h0.76
  text "SDIO" at 24.372,43.942 h1.2
  text "SPI" at 33.77,43.942 h1.2
  text "Morse Micro" at 43.2,36.375 h2.5
  text "12" at 23.356,36.115 h0.5
  text "20" at 40.755,36.115 h0.5
  text "DEBUG" at 63.996,24.876 h1.2 r90
  text "VDDIO" at 2.844,23.551 h1.27 r270
  text "VBAT" at 2.843,18.06 h1.27 r270
  text "31" at 40.755,17.954 h0.5
  text "VDDIO" at 15.5,17.25 h1.27
  text "GND" at 15.436,14.5 h1.27
  text "GND" at 60.516,14.182 h1.27
  text "VBAT" at 15.41,12.25 h1.27
  text "GND" at 49.784,11.176 h1.27
  text "GND" at 15.424,9.557 h1.27
  text "VFEM" at 15.372,7 h1.27
  text "MMECH06 V8" at 42.1,4.255 h2.29
  text "GND" at 15.101,2.572 h1.27
  text ".Layer_Name" at 39.5,-2.725 h1.52
Bottom Overlay:
  text "29" at 44.415,48.978 h0.8
  text "1" at 8.22,48.851 h0.8
  text "9" at 18.761,48.851 h0.8
  text "19" at 31.969,48.851 h0.8
  text "Morse Micro" at 54.852,39.624 h2.5
  text "MMECH06 V8" at 54.54,36.081 h1.8
  text ".Layer_Name" at 39.5,-2.725 h1.52
Top Paste:
  text ".Layer_Name" at 39.8,-2.85 h1.52
Bottom Paste:
  text ".Layer_Name" at 39.5,-2.725 h1.52
Top Solder:
  text ".Layer_Name" at 39.7,-2.75 h1.52
Bottom Solder:
  text ".Layer_Name" at 39.55,-2.9 h1.52
Drill Guide:
  text ".Layer_Name" at 39.575,-2.8 h1.52
Fab Notes:
  lines w0.1: 9.954,-21.343 9.954,-9.869 48.995,-9.869 48.995,-21.355 9.965,-21.355 ; 23.504,-21.319 23.504,-9.869 ; 23.504,-19.057 49.029,-19.057 ; 23.504,-16.769 49.029,-16.769 ; 23.504,-14.469 49.029,-14.469 ; 23.504,-12.169 49.029,-12.169 ; 41.479,-21.38 41.479,-19.08
  text "NOTES: UNLESS OTHERWISE SPECIFIED0" at -73.825,77.387 h1.52
  text "1. SPECIFICATIONS/TOLERANCES:" at -73.825,75.609 h1.52
  text "A. FABRICATE PER IPC-6012, CLASS 2, USING PROVIDED DATA FILES XXXXXXXX.ZIP" at -73.825,73.831 h1.52
  text "B. ALL SPECIFICATIONS USED SHALL BE PER THEIR LATEST REVISIONS." at -73.825,72.053 h1.52
  text "C. THE DIMENSIONS OF CIRCUIT FEATURES IN THE PROVIDED DATA MAY BE ADJUSTED" at -73.825,70.275 h1.52
  text "ONLY TO COMPENSATE FOR PROCESS TOLERANCES; ADDING, REMOVING OR RELOCATING" at -73.825,68.497 h1.52
  text "CIRCUIT FEATURES IS NOT ALLOWED" at -73.825,66.719 h1.52
  text "D. REMOVE ALL BURRS AND BREAK SHARP EDGES, .381 [.015] MAX RADIUS." at -73.825,64.941 h1.52
  text "E. PARENTHETICAL INFORMATION IS FOR REFERENCE ONLY." at -73.825,63.163 h1.52
  text "F. REPAIR OF PCB DEFECTS IS NOT PERMITTED." at -73.825,61.385 h1.52
  text "2. DIELECTRIC MATERIAL:" at -73.826,57.829 h1.52
  text "A. DIELECTRIC MATERIAL SHALL BE PER IPC-4101/99, /124, /126 OR /129 (RoHS COMPLIANT EPOXY-GLASS)" at -73.825,56.051 h1.52
  text "B. MINIMUM DIELECTRIC THICKNESS SHALL BE .051 [.002] FOR REFERENCED STACK-UP" at -73.825,54.273 h1.52
  text "DIMENSIONS OF.076 [.003] OR GREATER; IPC-6012 REQUIREMENTS SHALL OTHERWISE" at -73.825,52.495 h1.52
  text "APPLY. SINGLE-PLY CONSTRUCTION IS ALLOWED." at -73.825,50.717 h1.52
  text "C. SEE LAYER STACK-UP FOR REQUIRED COPPER WEIGHTS AND THE FINISHED PCB" at -73.825,48.939 h1.52
  text "THICKNESS. IF SPECIFIED, 1/3 OZ. STARTING FOIL MAY BE ACHIEVED BY 1/2 OZ. FOIL REDUCTION." at -73.825,47.161 h1.52
  text "D. FINISHED PCB THICKNESS SHALL BE MEASURED OVER LANDS AND/OR" at -73.825,45.383 h1.52
  text "CONDUCTORS NOT COVERED BY SOLDER MASK. IF SPECIFIED, 1/3 OZ. STARTING FOIL" at -73.825,43.605 h1.52
  text "MAY BE ACHIEVED BY 1/2 OZ. FOIL REDUCTION." at -73.825,41.827 h1.52
  text "3. DRILLING:" at -73.825,38.271 h1.52
  text "A. VIA DIAMETERS SHALL BE VERIFIED BEFORE PLATING; ALL OTHER HOLE" at -73.825,36.493 h1.52
  text "DIAMETERS ARE FINISHED DIMENSIONS." at -73.825,34.715 h1.52
  text "B. LAYER-TO-LAYER MISREGISTRATION SHALL BE .127 [.005] MAXIMUM." at -73.825,32.937 h1.52
  text "4. SOLDER MASK:" at -73.825,29.381 h1.52
  text "A. APPLY LPI SOLDER MASK OVER BARE COPPER USING PROVIDED DATA." at -73.825,27.603 h1.52
  text "B. SOLDER MASK SHALL BE PER IPC-SM-840, CLASS T, COLOR PURPLE." at -73.825,25.825 h1.52
  text "C. THE DIMENSIONS OF SOLDER MASK-DEFINED PADS ON PLANES AND/OR WIDE" at -73.825,24.047 h1.52
  text "CONDUCTORS SHALL NOT BE MODIFIED." at -73.825,22.269 h1.52
  text "5. SILKSCREEN/MARKING:" at -73.825,18.713 h1.52
  text "A. SILKSCREEN PCB PER PROVIDED DATA USING PERMANENT, NON-CONDUCTIVE" at -73.825,16.935 h1.52
  text "INK, COLOR WHITE." at -73.825,15.157 h1.52
  text "B. SUPPLIER ID AND TRACEABILITY INFORMATION SHALL NOT / BE APPLIED ON ANY PART OF THE PCB" at -73.799,10.744 h1.52
  text "C. INK SHALL NOT BE APPLIED TO ANY SOLDERABLE SURFACE." at -73.825,8.823 h1.52
  text "USING PROVIDED DATA." at -73.825,7.045 h1.52
  text "6. ELECTRICAL TEST:" at -73.825,3.489 h1.52
  text "A. DESIGN VERIFICATION SHALL BE DONE PRIOR TO PCB FABRICATION USING" at -73.825,1.711 h1.52
  text "GERBER DATA AND AN IPC-D-356 NETLIST." at -73.825,-0.067 h1.52
  text "B. ALL PCBS SHALL BE 100% ELECTRICALLY TESTED FOR OPENS AND SHORTS" at -73.825,-1.845 h1.52
  text "C. APPLY TEST STAMP IN NON-LEGEND AREA ON SECONDARY SIDE OF PCB." at -73.825,-3.623 h1.52
  text "7. FINAL FINISH:" at -73.825,-7.052 h1.52
  text "A. FINAL FINISH SHALL BE ELECTROLESS NICKEL/IMMERSION GOLD (ENIG) PER IPC-4552." at -73.825,-8.932 h1.52
  text "Project:" at 23.954,-11.469 h1.52
  text "MMECH06" at 30.579,-11.594 h2.03
  text "8. IMPEDANCE:" at -73.913,-11.677 h1.52
  text "A. IMPEDANCE TOLERANCE SHALL BE +/- 10%." at -73.913,-13.455 h1.52
  text "Company:" at 23.954,-13.769 h1.52
  text "Morse Micro" at 30.58,-13.894 h2.03
  text "B. SEE LAYER STACK-UP FOR IMPEDANCE REQUIREMENTS." at -73.913,-15.233 h1.52
  text "Drawn By:" at 23.954,-16.069 h1.52
  text "Chad O'Neill" at 30.579,-16.244 h2.03
  text "9. IF PANELIZATION SPECIFICATIONS ARE PROVIDED, THE PCBS SHALL BE DELIVERED IN PANEL" at -73.571,-18.355 h1.52
  text "FORM. HOWEVER, THESE SPECIFICATIONS MAY BE REPLACED BY SUPPLIER PREFERRED" at -73.571,-20.133 h1.52
  text "Date:" at 23.954,-20.655 h1.52
  text "Rev:" at 42.204,-20.755 h1.52
  text ".Print_Date" at 30.579,-20.93 h2.03
  text "8" at 45.454,-20.93 h2.03
  text "(SPECIFICATIONS AS APPROVED)." at -73.571,-21.911 h1.52
Board:
  lines w0.1: 19.484,0.008 21.977,0.008
  lines w0.25: 21.985,5.275 cw(c21.974,5.764) 21.485,5.753 cw(c21.996,5.764) 21.985,6.275 ; 21.985,5.275 21.977,0.008 cw(c21.977,0) 21.985,0 21.985,5.275 ; 21.985,6.275 29.115,6.275 ; 21.985,6.275 29.115,6.275 ; 29.115,0 31.693,0.006 29.115,0 ; 29.115,0 29.115,5.275 ccw(c29.1,5.789) 29.614,5.805 ccw(c29.129,5.79) 29.115,6.275
  lines w0.254: 21.985,0 3,0.011 cw(c3,3.011) 0,3.011 0,53.011 cw(c3,53.011) 3,56.011 62,56.011 cw(c62,53.011) 65,53.011 65,3.011 ; 29.115,0 61.988,0 ccw(c61.988,3) 64.988,3
Drill Drawing:
  text ".Layer_Name" at 39.55,-2.9 h1.52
